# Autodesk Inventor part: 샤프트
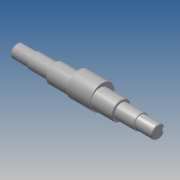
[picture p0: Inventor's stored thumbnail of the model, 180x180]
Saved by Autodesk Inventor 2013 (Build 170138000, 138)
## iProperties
Created: 2013-06
Part Number: 샤프트
Document SubType Name: Modeling
Designer: SeoGD™[esajin.kr]
Density: 7.86 g/cm^3
Material: 강철, 연강
Mass: 1327.93 g
Surface Area: 248.524 cm^2
Volume: 168.947 cm^3
Author: SeoGD™[esajin.kr]
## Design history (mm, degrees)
sketch "스케치1"
  geometry: L1 (-20.5, -41.331)-(-20.5, 32.669) reference; L2 (7.5, -30.031)-(7.5, 21.369) reference; L3 (135.5, -30.331)-(135.5, 21.669) reference; L4 (121.5, 21.369)-(121.5, -30.031) reference; L5 (184.5, -4.331)-(-57.5, -4.331); L6 (184.5, -4.331)-(184.5, 6.669); L7 (154.5, 8.169)-(121.5, 8.169); L8 (121.5, 8.169)-(121.5, 11.669); L9 (121.5, 11.669)-(7.5, 11.669); L10 (7.5, 11.669)-(7.5, 8.169); L11 (7.5, 8.169)-(-27.5, 8.169); L12 (-27.5, 8.169)-(-27.5, 6.669); L13 (-27.5, 6.669)-(-57.5, 6.669); L14 (-57.5, 6.669)-(-57.5, -4.331); L15 (154.5, 8.169)-(154.5, 6.669); L16 (154.5, 6.669)-(184.5, 6.669); C1 r 32.5 at (64.5, -4.331) reference; 1 further point
  constraints: 24 end point, 8 perpendicular, 5 point on line, 3 parallel, 2 collinear
  dimensions: "d1" = 25 diameter of L11 L5; "d2" = 32 diameter of L9 L5; "d3" = 22 diameter of L13 L5; "d4" = 35 distance of L10.end L11.end; "d5" = 30 distance of L12.end L13.end; "d15" = 33 distance of L7.start L7.end; "d26" = 30 distance of L15.end L6.end
revolve "회전1" sketch "스케치1" stored, may be unused: angle "d6" = 90 deg
node "작업 평면1"
sketch "스케치2"
  geometry: C1 r 16 at (0, 0) reference; C2 r 16 at (0, 0) reference; C3 r 20.75 at (0, 4); C4 r 16 at (0, 0) reference; 1 further point
  constraints: 1 centre point, 1 vertical alignment
  dimensions: "d8" = 41.5 diameter of C3; "d25" = 4 distance of C3.centre C1.centre
extrude "돌출1" join sketch "스케치2" stored distance "d9" = 40; taper "d10" = 0 deg
chamfer "모따기1" distance "d11" = 1; stored, may be unused: second distance "d12" = 2, angle "d13" = 45 deg
node "작업 평면2"
sketch "스케치3"
  geometry: L1 (-15, -10)-(-15, 10) reference; L2 (-15, 3)-(0, 3); L3 (0, -3)-(-15, -3); A1 r 3 centre (0, 0) between (0, -3) and (0, 3); 2 further points
  constraints: 4 end point, 2 perpendicular, 2 point on circle, 2 point on line, 2 tangent, 1 centre point, 1 horizontal alignment, 1 midpoint
  dimensions: "d16" = 18 dimension on A1 L1; "d17" = 6 distance between parallel lines of L3 L2
extrude "돌출2" cut sketch "스케치3" distance "d18" = 3.5; taper "d19" = 0 deg
node "작업 평면3"
node "솔리드1"
mirror "대칭1"
node "참조1"
node "참조2"
node "참조3"
node "참조4"
node "참조5"
node "투영된 루프1"
